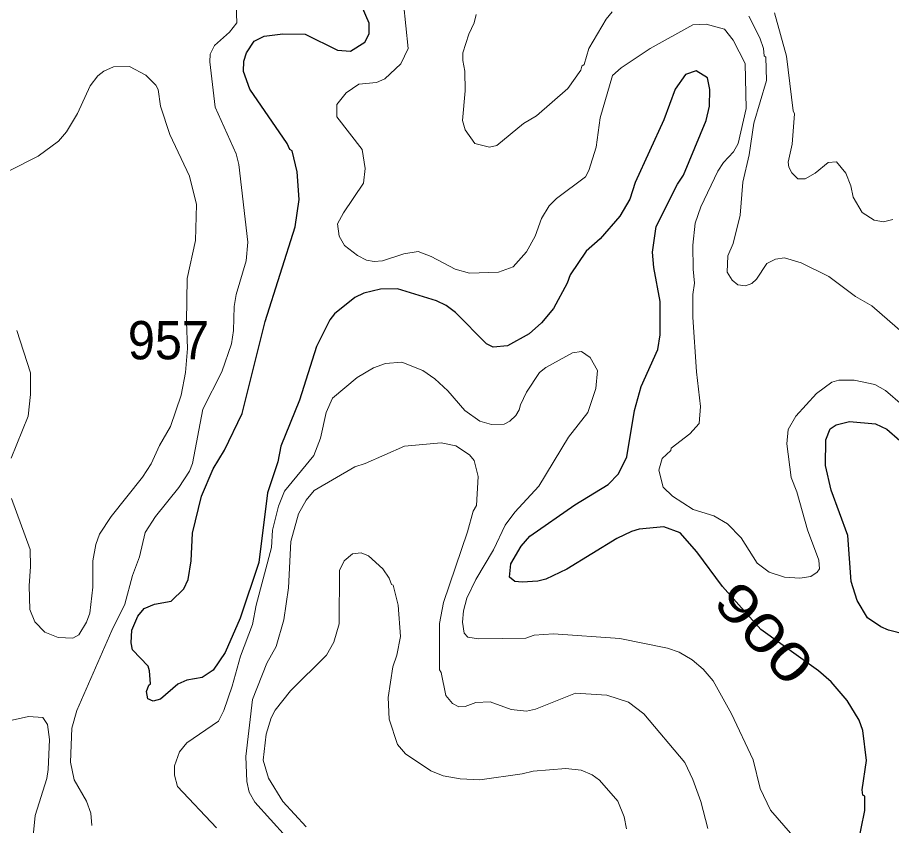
# Model space of a CAD drawing. Extents: x 447.8 to 473.9, y 7733.1 to 7760.8.
# Drawn here: x 456.079 to 457.905, y 7752.862 to 7754.55 of the extents above; entities that cross this region are included whole.
import ezdxf
from ezdxf.enums import TextEntityAlignment as Align

# ---------------------------------------------------------------- set-up
doc = ezdxf.new("R2010")
doc.units = 0
doc.header["$LTSCALE"] = 0.032
doc.layers.add('1', color=7, linetype='Continuous', lineweight=25)
doc.layers.add('2', color=7, linetype='Continuous', lineweight=13)
doc.layers.add('21', color=7, linetype='Continuous')
doc.layers.add('61', color=7, linetype='Continuous')

msp = doc.modelspace()

# ---------------------------------------------------------------- linework, layer by layer
at = {"layer": '1'}
for points in [[(456.6291, 7753.6547), (456.6224, 7753.6218), (456.6008, 7753.5574), (456.5831, 7753.4118), (456.544, 7753.2953), (456.5127, 7753.2239), (456.4877, 7753.1867), (456.4645, 7753.171), (456.4329, 7753.1656), (456.4138, 7753.1576), (456.3772, 7753.1262), (456.3622, 7753.1218), (456.3513, 7753.127), (456.3484, 7753.1422), (456.3529, 7753.1554), (456.3564, 7753.1584), (456.3548, 7753.1855), (456.3516, 7753.1952), (456.3194, 7753.2294), (456.3163, 7753.2436), (456.318, 7753.2702), (456.3305, 7753.2993), (456.3437, 7753.3158), (456.3647, 7753.3245), (456.3999, 7753.3311), (456.4263, 7753.3567), (456.4355, 7753.3762), (456.4413, 7753.4154), (456.4446, 7753.4731), (456.4632, 7753.5505), (456.4876, 7753.6071), (456.5112, 7753.6462), (456.5479, 7753.7229), (456.5959, 7753.9149), (456.6587, 7754.1132), (456.6672, 7754.1703), (456.6633, 7754.2282), (456.6529, 7754.2716), (456.648, 7754.2747), (456.6423, 7754.2869), (456.5641, 7754.4006), (456.5507, 7754.4379), (456.5514, 7754.4595), (456.5574, 7754.4768), (456.573, 7754.5013), (456.594, 7754.5117), (456.6328, 7754.5165), (456.6794, 7754.5157), (456.7472, 7754.4821), (456.7744, 7754.4804), (456.8046, 7754.499), (456.8132, 7754.5161), (456.8132, 7754.5385), (456.7971, 7754.5757)], [(457.8337, 7752.8184), (457.8488, 7752.8937), (457.8488, 7752.923), (457.8449, 7752.9256), (457.8433, 7752.9366), (457.852, 7752.9979), (457.8448, 7753.0607), (457.8373, 7753.0821), (457.8118, 7753.1235), (457.7786, 7753.1623), (457.7521, 7753.1855), (457.6316, 7753.2718), (457.5517, 7753.3615), (457.4976, 7753.4338), (457.4633, 7753.4734), (457.4288, 7753.4863), (457.3775, 7753.4815), (457.3612, 7753.4766), (457.3305, 7753.4617), (457.2263, 7753.3976), (457.1822, 7753.3767), (457.1656, 7753.3725), (457.133, 7753.3702), (457.1176, 7753.372), (457.1068, 7753.3809), (457.1095, 7753.4087), (457.1308, 7753.4459), (457.1493, 7753.4665), (457.243, 7753.5324), (457.3129, 7753.5746), (457.334, 7753.5968), (457.3517, 7753.6326), (457.3674, 7753.729), (457.3814, 7753.7791), (457.4162, 7753.8567), (457.4216, 7753.8876), (457.4216, 7753.9573), (457.408, 7754.0278), (457.4056, 7754.0603), (457.4128, 7754.1137), (457.4576, 7754.2019), (457.4703, 7754.2212), (457.5177, 7754.3349), (457.5246, 7754.3651), (457.525, 7754.3997), (457.5204, 7754.4244), (457.4965, 7754.4392), (457.474, 7754.4315), (457.4527, 7754.4006), (457.4287, 7754.3365), (457.3689, 7754.2057), (457.3577, 7754.1705), (457.3368, 7754.1351), (457.296, 7754.0879), (457.2667, 7754.0625), (457.2331, 7754.0127), (457.2267, 7753.995), (457.1985, 7753.9422), (457.1734, 7753.9123), (457.1477, 7753.8891), (457.1021, 7753.8641), (457.0725, 7753.8616), (457.0588, 7753.8688), (456.9938, 7753.9342), (456.9744, 7753.9488), (456.954, 7753.9587), (456.8725, 7753.9833), (456.8369, 7753.9825), (456.802, 7753.9745), (456.7837, 7753.9653)], [(456.7837, 7753.9653), (456.7413, 7753.9314), (456.7313, 7753.9189), (456.7037, 7753.8631), (456.6676, 7753.7509), (456.6291, 7753.6547)], [(457.9335, 7753.2612), (457.8985, 7753.27), (457.8822, 7753.2773), (457.8541, 7753.296), (457.8325, 7753.3324), (457.82, 7753.3721), (457.8136, 7753.4679), (457.7782, 7753.5629), (457.7665, 7753.614), (457.7671, 7753.668), (457.7761, 7753.6907), (457.7886, 7753.6991), (457.8165, 7753.706), (457.8713, 7753.7012), (457.8948, 7753.6905), (457.9222, 7753.6663)]]:
    msp.add_lwpolyline(points, dxfattribs=at)
at = {"layer": '2'}
for points in [[(456.5356, 7754.5775), (456.5372, 7754.5391), (456.5219, 7754.5201), (456.4904, 7754.4917), (456.4816, 7754.4737), (456.4806, 7754.4576), (456.4918, 7754.3629), (456.5354, 7754.2654), (456.5415, 7754.2435), (456.5598, 7754.0811), (456.5566, 7754.0419), (456.5359, 7753.9718), (456.5311, 7753.9467), (456.5301, 7753.8965), (456.5261, 7753.8685), (456.5057, 7753.81), (456.4657, 7753.7317), (456.4444, 7753.6185), (456.438, 7753.6028), (456.4161, 7753.5681), (456.367, 7753.5079), (456.3453, 7753.4743), (456.3339, 7753.4236), (456.3193, 7753.3844), (456.3033, 7753.3245), (456.2762, 7753.2693), (456.2025, 7753.1026), (456.1923, 7753.0652), (456.1897, 7752.9943), (456.1971, 7752.9577), (456.2231, 7752.9131), (456.2319, 7752.8875), (456.2344, 7752.8619)], [(456.8853, 7754.5801), (456.8949, 7754.486), (456.8799, 7754.4533), (456.846, 7754.4224), (456.8289, 7754.4146), (456.7917, 7754.4111)], [(457.0369, 7754.5565), (457.0331, 7754.5395), (457.0214, 7754.5158), (457.0089, 7754.4768), (457.0089, 7754.4604), (457.0136, 7754.4385), (457.0137, 7754.3969), (457.0081, 7754.3349), (457.0138, 7754.3158), (457.0341, 7754.2869), (457.0647, 7754.2792), (457.0801, 7754.2832), (457.1357, 7754.329), (457.163, 7754.345), (457.2282, 7754.4024), (457.2554, 7754.4402), (457.2576, 7754.4486), (457.2622, 7754.452), (457.2724, 7754.4856), (457.3082, 7754.5473), (457.3211, 7754.5624)], [(457.6068, 7754.5532), (457.6294, 7754.5081), (457.6372, 7754.4859), (457.6387, 7754.47), (457.642, 7754.4677), (457.6436, 7754.419), (457.617, 7754.3294), (457.6069, 7754.2634), (457.594, 7754.2061), (457.5882, 7754.1374), (457.5735, 7754.0782), (457.5629, 7754.0521), (457.5609, 7754.0182), (457.5717, 7754.0019), (457.5835, 7753.9918), (457.5992, 7753.9899), (457.6125, 7753.9947), (457.6228, 7754.0035), (457.6439, 7754.0363), (457.6622, 7754.0458), (457.6809, 7754.0481), (457.716, 7754.0379)], [(457.6604, 7754.56), (457.6854, 7754.4696), (457.699, 7754.3557), (457.7022, 7754.3492), (457.6973, 7754.2855), (457.6886, 7754.2481), (457.6901, 7754.2377), (457.6961, 7754.2256), (457.7089, 7754.2135), (457.7241, 7754.2136), (457.7449, 7754.225), (457.7725, 7754.2472), (457.7896, 7754.2486), (457.8093, 7754.2252), (457.8197, 7754.1984), (457.8245, 7754.1749), (457.8435, 7754.1429), (457.8682, 7754.1269), (457.8877, 7754.1237), (457.9073, 7754.1285)], [(456.8052, 7754.2346), (456.8013, 7754.2042), (456.7595, 7754.1425), (456.7476, 7754.1192), (456.7507, 7754.0935), (456.7618, 7754.0743), (456.7893, 7754.053), (456.8081, 7754.0436), (456.8241, 7754.0403), (456.8411, 7754.042), (456.8858, 7754.0568), (456.9156, 7754.0612), (456.9427, 7754.0509), (456.9933, 7754.0249), (457.0229, 7754.0163), (457.0838, 7754.0186), (457.1143, 7754.0297), (457.1424, 7754.0611), (457.1603, 7754.0932), (457.1732, 7754.1303), (457.1897, 7754.157), (457.2049, 7754.172), (457.265, 7754.2173), (457.2724, 7754.2307), (457.2877, 7754.2792), (457.2959, 7754.3408), (457.3217, 7754.4292), (457.3397, 7754.4456), (457.4006, 7754.4855), (457.4895, 7754.5354), (457.5174, 7754.5364), (457.5555, 7754.526), (457.5741, 7754.5032), (457.5987, 7754.454), (457.6011, 7754.3606), (457.5843, 7754.2872), (457.5748, 7754.2698), (457.5538, 7754.2473), (457.5419, 7754.2294), (457.506, 7754.1548), (457.4942, 7754.1207), (457.4898, 7754.0747), (457.4899, 7754.0244), (457.493, 7753.9955), (457.4898, 7753.9716), (457.4898, 7753.9241), (457.4969, 7753.8098), (457.5058, 7753.7376), (457.5025, 7753.7024), (457.4836, 7753.6806), (457.444, 7753.6505), (457.4439, 7753.6458), (457.4257, 7753.629), (457.4185, 7753.6046), (457.4274, 7753.5687), (457.4468, 7753.5499), (457.4901, 7753.5223), (457.5337, 7753.5093), (457.5622, 7753.4925), (457.5905, 7753.4634), (457.6238, 7753.4103), (457.649, 7753.3911), (457.6809, 7753.3813), (457.713, 7753.379), (457.7357, 7753.3823), (457.7494, 7753.3911), (457.7541, 7753.3985), (457.7526, 7753.4166), (457.7289, 7753.48), (457.707, 7753.559), (457.6946, 7753.5894), (457.6862, 7753.6596), (457.6888, 7753.6898), (457.7049, 7753.7175), (457.7476, 7753.7651), (457.78, 7753.7885), (457.7944, 7753.7925), (457.8264, 7753.7924), (457.8697, 7753.7837), (457.8921, 7753.7709), (457.9272, 7753.7406)], [(456.0629, 7754.2304), (456.1222, 7754.2607), (456.1647, 7754.292), (456.1815, 7754.3112), (456.204, 7754.3497), (456.2306, 7754.4077), (456.2468, 7754.4285), (456.2595, 7754.4382), (456.2794, 7754.4474), (456.313, 7754.4482), (456.347, 7754.4296), (456.3678, 7754.4088), (456.3724, 7754.3999), (456.3777, 7754.3652), (456.3967, 7754.3058), (456.4384, 7754.2188), (456.4524, 7754.1596), (456.451, 7754.0842), (456.4333, 7754.005), (456.4317, 7753.9145), (456.434, 7753.8591), (456.4299, 7753.8088), (456.4205, 7753.7616), (456.3987, 7753.6956), (456.3757, 7753.6558), (456.3582, 7753.6176), (456.3398, 7753.5896), (456.2747, 7753.5075), (456.2502, 7753.4705), (456.2427, 7753.4494), (456.2361, 7753.415), (456.236, 7753.3599), (456.2296, 7753.306), (456.2232, 7753.2871), (456.2068, 7753.2602), (456.1945, 7753.2532), (456.1641, 7753.2551), (456.1356, 7753.2663), (456.1153, 7753.2873), (456.1048, 7753.3134), (456.1031, 7753.3632), (456.1063, 7753.403), (456.1054, 7753.4391), (456.066, 7753.5452)], [(456.7917, 7754.4111), (456.7657, 7754.3927), (456.7459, 7754.3686), (456.7462, 7754.3431), (456.7987, 7754.2743), (456.8052, 7754.2346)], [(457.716, 7754.0379), (457.7735, 7754.009), (457.8294, 7753.9677), (457.8631, 7753.9477), (457.9705, 7753.8546), (458.0277, 7753.7908)], [(456.0657, 7753.6293), (456.1012, 7753.7177), (456.1062, 7753.7629), (456.1062, 7753.8078), (456.0777, 7753.8965)], [(456.4942, 7752.8575), (456.4128, 7752.9434), (456.4069, 7752.9673), (456.4069, 7752.9869), (456.4174, 7753.016), (456.4326, 7753.035), (456.4984, 7753.0798), (456.51, 7753.1022), (456.5275, 7753.1529), (456.545, 7753.2161), (456.5695, 7753.2822), (456.5772, 7753.3227), (456.6095, 7753.4428), (456.6115, 7753.479), (456.6241, 7753.529), (456.6367, 7753.5606), (456.698, 7753.6353), (456.7117, 7753.6715), (456.7238, 7753.7254), (456.7368, 7753.7553), (456.7886, 7753.798), (456.8223, 7753.8183), (456.8478, 7753.8276), (456.882, 7753.83), (456.9253, 7753.8125), (456.9507, 7753.7951), (456.9775, 7753.77), (457.0134, 7753.7295), (457.0447, 7753.7066), (457.0693, 7753.6997), (457.0952, 7753.7005), (457.1071, 7753.7067), (457.1195, 7753.7186), (457.127, 7753.7306), (457.1292, 7753.7414), (457.1418, 7753.7678), (457.1694, 7753.8087), (457.1828, 7753.8192), (457.2383, 7753.8494), (457.2571, 7753.8525), (457.275, 7753.8402), (457.2907, 7753.813), (457.2867, 7753.775), (457.2702, 7753.7252)], [(457.2702, 7753.7252), (457.2301, 7753.6733), (457.1679, 7753.5712), (457.1178, 7753.5168), (457.0974, 7753.4897), (457.0733, 7753.4383)], [(457.5208, 7752.8561), (457.5062, 7752.9121), (457.4896, 7752.9584), (457.4731, 7752.9939), (457.3869, 7753.0954), (457.3551, 7753.12), (457.3102, 7753.1344), (457.2446, 7753.1385), (457.1611, 7753.1049), (457.1422, 7753.1009), (457.11, 7753.1044), (457.0665, 7753.1208), (457.0361, 7753.1192), (457.0139, 7753.1105), (457.0006, 7753.1101), (456.9877, 7753.1172), (456.9738, 7753.1336), (456.964, 7753.1818), (456.96, 7753.187), (456.96, 7753.2839), (456.9685, 7753.3278), (457.0188, 7753.4754), (457.031, 7753.5186), (457.0377, 7753.5308), (457.0408, 7753.5914), (457.0328, 7753.6247), (457.0227, 7753.6367), (456.9946, 7753.6554), (456.9639, 7753.6618), (456.8873, 7753.6548), (456.8052, 7753.6186), (456.7834, 7753.6118), (456.6985, 7753.5622), (456.6819, 7753.542), (456.6659, 7753.5131), (456.6499, 7753.4558), (456.6449, 7753.359), (456.6352, 7753.2916), (456.6195, 7753.2361), (456.5997, 7753.2012), (456.57, 7753.125)], [(457.3512, 7752.8553), (457.346, 7752.8802), (457.333, 7752.9126), (457.2944, 7752.9571), (457.2791, 7752.9681), (457.2562, 7752.9776), (457.2243, 7752.9813), (457.156, 7752.9757), (457.1327, 7752.9699), (457.0444, 7752.9574), (457.0037, 7752.9599), (456.9678, 7752.966), (456.9421, 7752.9762), (456.8891, 7753.0121), (456.8726, 7753.0311), (456.855, 7753.0845), (456.8533, 7753.1296), (456.8629, 7753.1935), (456.8714, 7753.2182), (456.8789, 7753.2572), (456.874, 7753.3227), (456.8637, 7753.364), (456.8599, 7753.3655), (456.8549, 7753.3789), (456.8417, 7753.3984), (456.8119, 7753.4252), (456.797, 7753.4318), (456.7784, 7753.4298), (456.7615, 7753.4153), (456.7517, 7753.3952), (456.7507, 7753.2832), (456.7393, 7753.2448), (456.7244, 7753.2177), (456.6492, 7753.1436), (456.617, 7753.1029), (456.6088, 7753.087), (456.5985, 7753.0531), (456.592, 7752.9986), (456.6034, 7752.961), (456.633, 7752.9122), (456.6819, 7752.8593)], [(457.0733, 7753.4383), (457.036, 7753.3763), (457.0171, 7753.337), (457.0104, 7753.3108), (457.0081, 7753.2866), (457.0122, 7753.2637), (457.0192, 7753.2559), (457.042, 7753.2523), (457.1406, 7753.2538), (457.1583, 7753.2595), (457.1987, 7753.2627), (457.3372, 7753.2531), (457.4367, 7753.2325), (457.4611, 7753.224), (457.4883, 7753.2083), (457.5111, 7753.189), (457.5317, 7753.1646), (457.57, 7753.0957), (457.6158, 7752.9991), (457.6305, 7752.9396), (457.6521, 7752.8944), (457.6938, 7752.8458)], [(456.57, 7753.125), (456.5555, 7753.006), (456.5576, 7752.9542), (456.5628, 7752.9314), (456.5744, 7752.9111), (456.6401, 7752.8386)], [(456.0758, 7752.4511), (456.0933, 7752.5278), (456.0983, 7752.5737), (456.1077, 7752.6179), (456.1072, 7752.6302), (456.1172, 7752.6737), (456.1301, 7752.7062), (456.1287, 7752.735), (456.1128, 7752.7956), (456.1111, 7752.8334), (456.1159, 7752.8831), (456.14, 7752.96), (456.1432, 7752.9792), (456.1455, 7753.0419), (456.1415, 7753.0734), (456.1319, 7753.0878), (456.1018, 7753.0897), (456.0674, 7753.0822)]]:
    msp.add_lwpolyline(points, dxfattribs=at)

# ---------------------------------------------------------------- texts
at = {"layer": '21', "width": 0.95}
msp.add_text('957', height=0.08, dxfattribs=at).set_placement((456.3093, 7753.8362))
at = {"layer": '61', "width": 1.35}
msp.add_text('900', height=0.08, rotation=311.955, dxfattribs=at).set_placement((457.6089, 7753.2372), align=Align.CENTER)

doc.saveas('drawing.dxf')
